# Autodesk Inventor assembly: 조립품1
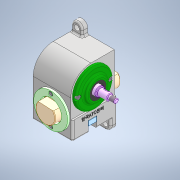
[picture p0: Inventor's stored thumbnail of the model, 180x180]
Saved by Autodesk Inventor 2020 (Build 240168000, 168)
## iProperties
Created: 2023-09
Part Number: 조립품1
Document SubType Name: Assembly
Designer: oem
Author: oem
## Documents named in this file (11)
- C:\Users\oem\Desktop\730906V1009\조립품1.iam
- C:\Users\oem\Desktop\730906V1009\본체.ipt
- C:\Users\oem\Desktop\730906V1009\가이드 부시.ipt
- C:\Users\oem\Desktop\730906V1009\부시 커버.ipt
- C:\Users\oem\Desktop\730906V1009\볼트 M4.ipt
- C:\Users\oem\Desktop\730906V1009\래크.ipt
- C:\Users\oem\Desktop\730906V1009\스톱퍼.ipt
- C:\Users\oem\Desktop\730906V1009\베어링 6003.ipt
- C:\Users\oem\Desktop\730906V1009\피니언.ipt
- C:\Users\oem\Desktop\730906V1009\앞커버.ipt
- C:\Users\oem\Desktop\730906V1009\오일 실 17 30 5.ipt
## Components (3 placed, 2 different names)
1. 가이드 부시:1
2. 가이드 부시:2
3. 피니언:1
